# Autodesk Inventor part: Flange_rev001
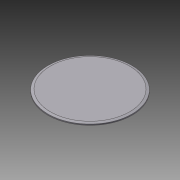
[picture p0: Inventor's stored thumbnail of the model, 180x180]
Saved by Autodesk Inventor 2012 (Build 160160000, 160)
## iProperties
Created: 2011-12
Part Number: Flange_rev001
Document SubType Name: Modeling
Designer: Alex
Density: 2.71 g/cm^3
Material: Aluminum-6061
Mass: 7.79956 g
Surface Area: 39.9297 cm^2
Volume: 2.87807 cm^3
Author: Alex
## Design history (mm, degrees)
sketch "Sketch1"
  geometry: L1 (0, 0)-(34.442, 0); L2 (34.442, 0)-(36.538, -0.601); L3 (0, -1.578)-(0, 0); L4 (36.538, -0.601)-(36.538, -1.578); L5 (0, -1.893)-(0, 0.316) reference; L6 (36.538, -1.578)-(0, -1.578); 1 further point
  constraints: 10 end point, 3 perpendicular, 2 point on line, 1 horizontal
  dimensions: "d1" = 34.4424 distance of L1.end point (0, 0); "d2" = 164 deg angle of L2 L1; "d11" = 0.60087 vertical distance of L2.end L1.end (derived); "d12" = 1.57752 distance between parallel lines of L6 L1; "d13" = 2.0955 horizontal distance of L2.end L1.end; "d14" = 0.97664 distance of L4.end L2.end (derived); "d15" = 36.5379 distance from line of L4.end L3 (derived)
revolve "Revolution1" sketch "Sketch1" stored, may be unused: angle "d8" = 90 deg
body "Solid1"
